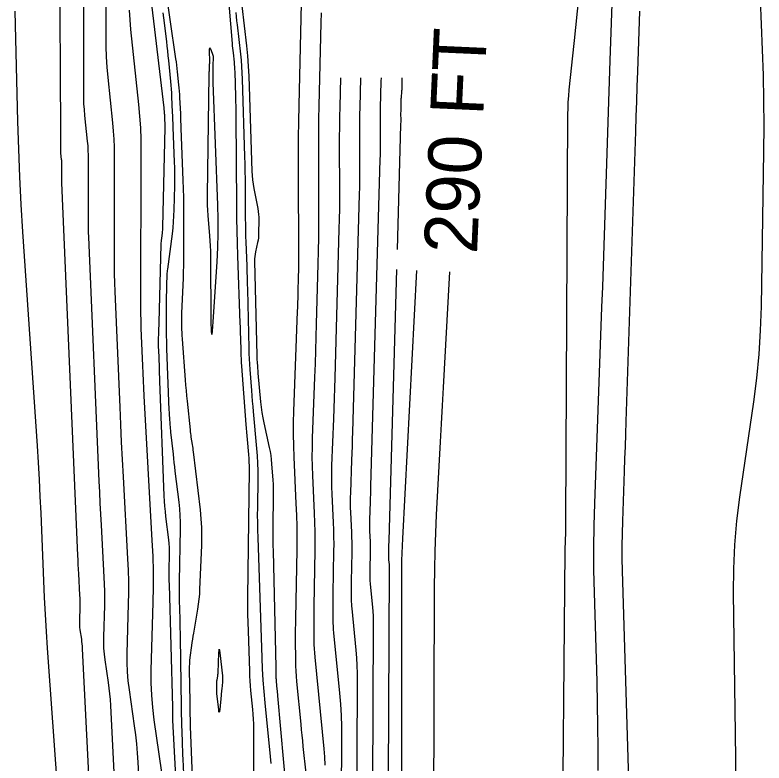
# Model space of a CAD drawing. Extents: x 1768942 to 1774819, y 723037 to 732099.
# Drawn here: x 1770850.2 to 1770934.8, y 724021.2 to 724105.6 of the extents above; entities that cross this region are included whole.
import ezdxf

# ---------------------------------------------------------------- set-up
doc = ezdxf.new("R2010")
doc.units = 0
doc.layers.add('R_Contour Annot', color=7, linetype='Continuous')
doc.layers.add('R_Contours', color=7, linetype='Continuous')

msp = doc.modelspace()

# ---------------------------------------------------------------- linework, layer by layer
at = {"layer": 'R_Contours'}
for points in [[(1770859.762, 723996.003), (1770857.868, 724034.096), (1770857.852, 724034.366), (1770857.829, 724034.635), (1770857.799, 724034.903), (1770857.763, 724035.171), (1770857.607, 724036.241), (1770857.573, 724036.509), (1770857.552, 724036.777), (1770857.542, 724037.047), (1770857.543, 724037.316), (1770857.584, 724038.787), (1770857.589, 724039.123), (1770857.588, 724039.458), (1770857.58, 724039.793), (1770857.565, 724040.128), (1770857.43, 724042.558), (1770857.402, 724043.075), (1770857.376, 724043.592), (1770857.352, 724044.109), (1770857.329, 724044.626), (1770855.534, 724086.687), (1770855.528, 724086.822), (1770855.525, 724086.957), (1770855.523, 724087.092), (1770855.523, 724087.227), (1770855.526, 724088.794), (1770855.525, 724088.919), (1770855.52, 724089.045), (1770855.512, 724089.17), (1770855.5, 724089.295), (1770855.426, 724090), (1770855.411, 724090.159), (1770855.401, 724090.319), (1770855.395, 724090.478), (1770855.394, 724090.638), (1770855.399, 724091.606), (1770855.4, 724091.821), (1770855.401, 724092.036), (1770855.4, 724092.25), (1770855.399, 724092.465), (1770855.166, 724132.363)], [(1770857.856, 724125.104), (1770857.977, 724104.494), (1770857.981, 724103.605), (1770857.982, 724102.715), (1770857.981, 724101.826), (1770857.977, 724100.936), (1770857.955, 724096.925), (1770857.961, 724096.263), (1770857.985, 724095.601), (1770858.027, 724094.94), (1770858.087, 724094.28), (1770858.396, 724091.361), (1770858.444, 724090.842), (1770858.477, 724090.323), (1770858.497, 724089.803), (1770858.503, 724089.282), (1770858.488, 724082.792), (1770858.49, 724082.231), (1770858.498, 724081.671), (1770858.513, 724081.111), (1770858.533, 724080.551), (1770859.71, 724052.988), (1770859.765, 724051.746), (1770859.824, 724050.505), (1770859.886, 724049.263), (1770859.953, 724048.022), (1770860.277, 724042.183), (1770860.314, 724041.379), (1770860.333, 724040.574), (1770860.336, 724039.77), (1770860.322, 724038.964), (1770860.225, 724035.432), (1770860.222, 724034.783), (1770860.246, 724034.137), (1770860.298, 724033.492), (1770860.378, 724032.848), (1770860.753, 724030.278), (1770860.84, 724029.635), (1770860.911, 724028.99), (1770860.966, 724028.344), (1770861.006, 724027.696), (1770862.207, 724003.529)], [(1770916.065, 724020.339), (1770916.074, 724022.853), (1770916.059, 724025.366), (1770916.02, 724027.879), (1770915.957, 724030.392), (1770915.657, 724040.443), (1770915.603, 724042.955), (1770915.591, 724045.468), (1770915.621, 724047.98), (1770915.692, 724050.492), (1770916.507, 724072.621), (1770916.592, 724074.942), (1770916.674, 724077.263), (1770916.753, 724079.584), (1770916.831, 724081.905), (1770917.136, 724091.191), (1770917.213, 724093.512), (1770917.291, 724095.833), (1770917.37, 724098.154), (1770917.45, 724100.476), (1770918.191, 724121.776)], [(1770914.509, 724113.785), (1770913.356, 724102.74), (1770913.283, 724102.045), (1770913.211, 724101.349), (1770913.139, 724100.654), (1770913.067, 724099.959), (1770912.781, 724097.177), (1770912.718, 724096.481), (1770912.672, 724095.784), (1770912.643, 724095.087), (1770912.631, 724094.388), (1770912.404, 724048.562), (1770912.401, 724048.23), (1770912.396, 724047.898), (1770912.387, 724047.566), (1770912.376, 724047.234), (1770912.304, 724045.268), (1770912.304, 724045.256), (1770912.304, 724045.243), (1770912.304, 724045.231), (1770912.304, 724045.219), (1770912.305, 724045.17), (1770912.306, 724045.158), (1770912.306, 724045.146), (1770912.306, 724045.133), (1770912.306, 724045.121), (1770911.991, 724007.151)], [(1770931.657, 724018.758), (1770931.62, 724021.635), (1770931.582, 724024.511), (1770931.374, 724040.418), (1770931.392, 724043.126), (1770931.517, 724045.827), (1770931.748, 724048.52), (1770932.085, 724051.207), (1770933.648, 724061.94), (1770933.995, 724064.627), (1770934.255, 724067.32), (1770934.428, 724070.021), (1770934.513, 724072.729), (1770934.783, 724090.222), (1770934.807, 724093.088), (1770934.793, 724095.954), (1770934.739, 724098.819), (1770934.646, 724101.684), (1770934.196, 724113.142)], [(1770864.653, 724011.056), (1770864.143, 724021.296), (1770864.08, 724022.322), (1770863.992, 724023.345), (1770863.88, 724024.367), (1770863.744, 724025.385), (1770863.149, 724029.456), (1770863.022, 724030.474), (1770862.939, 724031.496), (1770862.901, 724032.52), (1770862.907, 724033.547), (1770863.061, 724039.142), (1770863.083, 724040.416), (1770863.078, 724041.691), (1770863.047, 724042.965), (1770862.99, 724044.239), (1770862.477, 724053.485), (1770862.371, 724055.451), (1770862.271, 724057.417), (1770862.178, 724059.384), (1770862.091, 724061.35), (1770861.533, 724074.416), (1770861.497, 724075.4), (1770861.471, 724076.385), (1770861.457, 724077.371), (1770861.453, 724078.356), (1770861.48, 724089.77), (1770861.469, 724090.686), (1770861.435, 724091.601), (1770861.375, 724092.514), (1770861.291, 724093.427), (1770860.749, 724098.561), (1770860.642, 724099.721), (1770860.568, 724100.883), (1770860.526, 724102.047), (1770860.517, 724103.212), (1770860.562, 724111.374)], [(1770867.08, 724109.586), (1770868.364, 724100.671), (1770868.415, 724100.306), (1770868.463, 724099.94), (1770868.508, 724099.575), (1770868.551, 724099.209), (1770868.714, 724097.743), (1770868.752, 724097.377), (1770868.783, 724097.01), (1770868.809, 724096.642), (1770868.827, 724096.274), (1770868.903, 724094.486), (1770868.921, 724094.065), (1770868.938, 724093.645), (1770868.955, 724093.224), (1770868.971, 724092.803), (1770869.193, 724086.961), (1770869.225, 724085.997), (1770869.248, 724085.032), (1770869.261, 724084.068), (1770869.266, 724083.104), (1770869.265, 724078.724), (1770869.261, 724078.02), (1770869.25, 724077.316), (1770869.231, 724076.613), (1770869.205, 724075.909), (1770869.038, 724071.977), (1770869.033, 724071.833), (1770869.03, 724071.689), (1770869.029, 724071.545), (1770869.03, 724071.401), (1770869.037, 724070.825), (1770869.039, 724070.681), (1770869.042, 724070.537), (1770869.046, 724070.393), (1770869.051, 724070.249), (1770869.074, 724069.641), (1770869.08, 724069.491), (1770869.088, 724069.342), (1770869.097, 724069.193), (1770869.107, 724069.044), (1770869.453, 724064.438), (1770869.5, 724063.831), (1770869.552, 724063.224), (1770869.608, 724062.618), (1770869.667, 724062.012), (1770869.996, 724058.792), (1770870.019, 724058.584), (1770870.045, 724058.377), (1770870.074, 724058.17), (1770870.106, 724057.964), (1770870.24, 724057.138), (1770870.272, 724056.932), (1770870.302, 724056.725), (1770870.33, 724056.518), (1770870.356, 724056.311), (1770871.124, 724049.768), (1770871.222, 724048.762), (1770871.281, 724047.754), (1770871.3, 724046.745), (1770871.279, 724045.734), (1770871.082, 724040.808), (1770871.05, 724040.238), (1770871, 724039.669), (1770870.931, 724039.103), (1770870.843, 724038.538), (1770870.379, 724035.839), (1770870.322, 724035.497), (1770870.268, 724035.155), (1770870.218, 724034.812), (1770870.171, 724034.469), (1770869.99, 724033.095), (1770869.951, 724032.752), (1770869.924, 724032.407), (1770869.91, 724032.062), (1770869.909, 724031.716), (1770869.961, 724028.15), (1770869.973, 724027.44), (1770869.988, 724026.73), (1770870.007, 724026.021), (1770870.03, 724025.311), (1770870.226, 724019.621)], [(1770865.373, 724109.064), (1770867.028, 724095.119), (1770867.036, 724095.048), (1770867.044, 724094.976), (1770867.052, 724094.905), (1770867.059, 724094.833), (1770867.091, 724094.518), (1770867.096, 724094.461), (1770867.101, 724094.403), (1770867.105, 724094.345), (1770867.107, 724094.288), (1770867.117, 724094.057), (1770867.12, 724093.999), (1770867.122, 724093.942), (1770867.124, 724093.884), (1770867.126, 724093.826), (1770867.145, 724093.33), (1770867.148, 724093.228), (1770867.15, 724093.126), (1770867.15, 724093.024), (1770867.149, 724092.922), (1770866.901, 724081.667), (1770866.895, 724081.504), (1770866.885, 724081.341), (1770866.87, 724081.179), (1770866.851, 724081.016), (1770866.764, 724080.368), (1770866.745, 724080.206), (1770866.73, 724080.043), (1770866.719, 724079.88), (1770866.712, 724079.717), (1770866.473, 724070.91), (1770866.445, 724069.876), (1770866.416, 724068.843), (1770866.411, 724068.585), (1770866.411, 724068.327), (1770866.414, 724068.069), (1770866.422, 724067.81), (1770866.495, 724065.905), (1770866.51, 724065.501), (1770866.525, 724065.097), (1770866.541, 724064.694), (1770866.556, 724064.29), (1770867.057, 724051.336), (1770867.086, 724050.754), (1770867.126, 724050.172), (1770867.179, 724049.591), (1770867.244, 724049.011), (1770867.567, 724046.365), (1770867.61, 724045.949), (1770867.639, 724045.533), (1770867.653, 724045.115), (1770867.652, 724044.697), (1770867.619, 724043.024), (1770867.614, 724042.605), (1770867.613, 724042.187), (1770867.617, 724041.768), (1770867.626, 724041.35), (1770868.003, 724027.481), (1770868.006, 724027.378), (1770868.008, 724027.276), (1770868.01, 724027.174), (1770868.012, 724027.072), (1770868.019, 724026.541), (1770868.02, 724026.5), (1770868.021, 724026.458), (1770868.022, 724026.417), (1770868.023, 724026.375), (1770868.029, 724026.209), (1770868.03, 724026.168), (1770868.032, 724026.127), (1770868.034, 724026.085), (1770868.036, 724026.044), (1770868.457, 724017.573)], [(1770877.215, 724014.005), (1770877.205, 724025.07), (1770877.197, 724025.611), (1770877.177, 724026.151), (1770877.143, 724026.691), (1770877.095, 724027.23), (1770876.879, 724029.384), (1770876.829, 724029.923), (1770876.789, 724030.463), (1770876.757, 724031.003), (1770876.735, 724031.543), (1770876.582, 724036.106), (1770876.556, 724037.047), (1770876.541, 724037.988), (1770876.535, 724038.929), (1770876.541, 724039.871), (1770876.703, 724054.289), (1770876.703, 724054.717), (1770876.692, 724055.143), (1770876.669, 724055.569), (1770876.637, 724055.995), (1770876.483, 724057.697), (1770876.446, 724058.123), (1770876.41, 724058.549), (1770876.375, 724058.975), (1770876.342, 724059.401), (1770875.842, 724065.98), (1770875.814, 724066.384), (1770875.791, 724066.788), (1770875.774, 724067.192), (1770875.762, 724067.597), (1770875.723, 724069.216), (1770875.713, 724069.62), (1770875.701, 724070.025), (1770875.688, 724070.429), (1770875.673, 724070.834), (1770875.387, 724078.448), (1770875.34, 724079.852), (1770875.304, 724081.256), (1770875.28, 724082.66), (1770875.266, 724084.065), (1770875.21, 724094.193), (1770875.205, 724094.748), (1770875.197, 724095.303), (1770875.185, 724095.858), (1770875.17, 724096.414), (1770875.084, 724099.212), (1770875.074, 724099.478), (1770875.057, 724099.743), (1770875.036, 724100.008), (1770875.008, 724100.273), (1770874.889, 724101.331), (1770874.86, 724101.595), (1770874.833, 724101.86), (1770874.809, 724102.125), (1770874.786, 724102.39), (1770874.283, 724108.645)], [(1770875.594, 724108.942), (1770876.364, 724102.132), (1770876.481, 724100.987), (1770876.575, 724099.84), (1770876.646, 724098.691), (1770876.693, 724097.541), (1770876.985, 724087.971), (1770877.01, 724087.479), (1770877.055, 724086.99), (1770877.121, 724086.502), (1770877.206, 724086.017), (1770877.652, 724083.762), (1770877.708, 724083.436), (1770877.746, 724083.109), (1770877.767, 724082.781), (1770877.77, 724082.451), (1770877.747, 724081.002), (1770877.736, 724080.735), (1770877.711, 724080.469), (1770877.673, 724080.205), (1770877.621, 724079.942), (1770877.386, 724078.895), (1770877.335, 724078.632), (1770877.301, 724078.368), (1770877.283, 724078.102), (1770877.281, 724077.835), (1770877.534, 724067.165), (1770877.539, 724067.002), (1770877.546, 724066.838), (1770877.556, 724066.675), (1770877.567, 724066.511), (1770877.617, 724065.858), (1770877.629, 724065.695), (1770877.642, 724065.531), (1770877.656, 724065.368), (1770877.671, 724065.205), (1770877.964, 724061.945), (1770878.027, 724061.349), (1770878.11, 724060.755), (1770878.21, 724060.165), (1770878.33, 724059.577), (1770878.942, 724056.802), (1770879.034, 724056.346), (1770879.109, 724055.889), (1770879.168, 724055.428), (1770879.21, 724054.966), (1770879.346, 724053.11), (1770879.375, 724052.646), (1770879.394, 724052.182), (1770879.403, 724051.718), (1770879.402, 724051.253), (1770879.36, 724047.925), (1770879.354, 724047.215), (1770879.355, 724046.506), (1770879.362, 724045.796), (1770879.376, 724045.086), (1770879.694, 724032.001), (1770879.697, 724031.866), (1770879.699, 724031.73), (1770879.7, 724031.595), (1770879.7, 724031.459), (1770879.699, 724030.917), (1770879.701, 724030.782), (1770879.706, 724030.647), (1770879.715, 724030.511), (1770879.726, 724030.377), (1770879.812, 724029.525), (1770879.831, 724029.338), (1770879.849, 724029.151), (1770879.867, 724028.964), (1770879.884, 724028.777), (1770880.898, 724017.509)], [(1770882.552, 724106.919), (1770882.276, 724095.421), (1770882.238, 724093.601), (1770882.214, 724091.781), (1770882.203, 724089.961), (1770882.205, 724088.14), (1770882.25, 724078.232), (1770882.25, 724077.725), (1770882.246, 724077.217), (1770882.238, 724076.71), (1770882.226, 724076.203), (1770882.168, 724074.176), (1770882.153, 724073.669), (1770882.137, 724073.162), (1770882.119, 724072.655), (1770882.101, 724072.148), (1770881.684, 724060.916), (1770881.649, 724059.611), (1770881.642, 724058.307), (1770881.663, 724057.003), (1770881.711, 724055.699), (1770881.961, 724050.484), (1770882.012, 724049.18), (1770882.042, 724047.875), (1770882.051, 724046.571), (1770882.039, 724045.266), (1770881.9, 724037.503), (1770881.892, 724036.91), (1770881.886, 724036.317), (1770881.885, 724035.724), (1770881.887, 724035.131), (1770881.903, 724032.759), (1770881.914, 724032.167), (1770881.938, 724031.575), (1770881.976, 724030.984), (1770882.027, 724030.393), (1770882.502, 724025.581), (1770882.564, 724024.953), (1770882.626, 724024.324), (1770882.689, 724023.696), (1770882.753, 724023.068), (1770883.057, 724020.056)], [(1770850.233, 724106.044), (1770850.53, 724093.578), (1770850.621, 724090.463), (1770850.746, 724087.348), (1770850.905, 724084.236), (1770851.097, 724081.124), (1770852.72, 724056.999), (1770852.842, 724055.096), (1770852.951, 724053.192), (1770853.048, 724051.287), (1770853.133, 724049.382), (1770853.447, 724041.76), (1770853.533, 724039.855), (1770853.634, 724037.951), (1770853.749, 724036.047), (1770853.879, 724034.145), (1770856.967, 723991.357)], [(1770863.121, 724106.164), (1770863.191, 724105.065), (1770863.291, 724103.967), (1770864.187, 724095.492), (1770864.307, 724094.186), (1770864.392, 724092.879), (1770864.442, 724091.569), (1770864.456, 724090.258), (1770864.416, 724072.793), (1770864.419, 724071.946), (1770864.431, 724071.1), (1770864.453, 724070.253), (1770864.485, 724069.407), (1770864.629, 724066.022), (1770864.667, 724065.175), (1770864.707, 724064.329), (1770864.75, 724063.483), (1770864.795, 724062.638), (1770865.702, 724046.295), (1770865.781, 724044.552), (1770865.823, 724042.808), (1770865.829, 724041.063), (1770865.8, 724039.319), (1770865.589, 724031.662), (1770865.581, 724030.257), (1770865.633, 724028.855), (1770865.746, 724027.457), (1770865.919, 724026.063), (1770867.052, 724018.318)], [(1770875.172, 724105.901), (1770875.216, 724105.43), (1770875.263, 724104.959), (1770875.315, 724104.489), (1770875.686, 724101.203), (1770875.758, 724100.498), (1770875.816, 724099.792), (1770875.86, 724099.085), (1770875.889, 724098.377), (1770876.156, 724089.63), (1770876.179, 724088.797), (1770876.196, 724087.964), (1770876.209, 724087.131), (1770876.216, 724086.297), (1770876.236, 724082.631), (1770876.243, 724081.965), (1770876.254, 724081.298), (1770876.271, 724080.632), (1770876.294, 724079.966), (1770876.394, 724077.301), (1770876.418, 724076.635), (1770876.439, 724075.969), (1770876.459, 724075.302), (1770876.476, 724074.636), (1770876.633, 724068.009), (1770876.651, 724067.411), (1770876.677, 724066.813), (1770876.711, 724066.216), (1770876.752, 724065.619), (1770876.933, 724063.233), (1770876.98, 724062.637), (1770877.028, 724062.04), (1770877.079, 724061.444), (1770877.131, 724060.848), (1770877.506, 724056.69), (1770877.57, 724055.855), (1770877.614, 724055.02), (1770877.636, 724054.183), (1770877.637, 724053.346), (1770877.599, 724049.995), (1770877.594, 724049.158), (1770877.599, 724048.32), (1770877.613, 724047.483), (1770877.636, 724046.645), (1770878.089, 724033.083), (1770878.142, 724031.805), (1770878.217, 724030.528), (1770878.313, 724029.252), (1770878.43, 724027.978), (1770879.037, 724021.935), (1770879.107, 724021.136)], [(1770920.759, 724106.037), (1770920.523, 724099.249), (1770920.464, 724097.552), (1770920.406, 724095.855), (1770920.349, 724094.158), (1770920.293, 724092.461), (1770919.217, 724059.726), (1770919.17, 724058.322), (1770919.122, 724056.919), (1770919.072, 724055.516), (1770919.021, 724054.112), (1770918.815, 724048.499), (1770918.775, 724047.096), (1770918.758, 724045.692), (1770918.765, 724044.289), (1770918.795, 724042.885), (1770919.832, 724008.14)], [(1770866.934, 724105.836), (1770867.006, 724105.301), (1770867.324, 724102.618), (1770867.387, 724102.082), (1770867.447, 724101.546), (1770867.504, 724101.009), (1770867.559, 724100.473), (1770867.797, 724098.113), (1770867.837, 724097.683), (1770867.871, 724097.251), (1770867.899, 724096.82), (1770867.92, 724096.387), (1770867.994, 724094.658), (1770868.012, 724094.225), (1770868.03, 724093.793), (1770868.047, 724093.361), (1770868.064, 724092.928), (1770868.211, 724089.037), (1770868.232, 724088.36), (1770868.242, 724087.682), (1770868.243, 724087.005), (1770868.233, 724086.327), (1770868.173, 724083.616), (1770868.149, 724082.939), (1770868.106, 724082.263), (1770868.045, 724081.589), (1770867.965, 724080.917), (1770867.435, 724076.942), (1770867.417, 724076.789), (1770867.402, 724076.635), (1770867.392, 724076.481), (1770867.386, 724076.326), (1770867.352, 724075.089), (1770867.302, 724073.23), (1770867.294, 724072.868), (1770867.289, 724072.507), (1770867.288, 724072.145), (1770867.291, 724071.784), (1770867.315, 724069.795), (1770867.321, 724069.343), (1770867.331, 724068.891), (1770867.344, 724068.439), (1770867.359, 724067.988), (1770867.622, 724060.996), (1770867.63, 724060.789), (1770867.641, 724060.582), (1770867.654, 724060.375), (1770867.668, 724060.169), (1770867.73, 724059.342), (1770867.747, 724059.136), (1770867.765, 724058.929), (1770867.785, 724058.723), (1770867.806, 724058.517), (1770868.076, 724056.052), (1770868.129, 724055.573), (1770868.183, 724055.094), (1770868.24, 724054.615), (1770868.297, 724054.136), (1770868.727, 724050.615), (1770868.805, 724049.868), (1770868.857, 724049.119), (1770868.882, 724048.37), (1770868.88, 724047.619), (1770868.765, 724041.69), (1770868.758, 724041.161), (1770868.757, 724040.632), (1770868.762, 724040.103), (1770868.773, 724039.575), (1770868.831, 724037.46), (1770868.844, 724036.931), (1770868.856, 724036.402), (1770868.866, 724035.874), (1770868.875, 724035.345), (1770868.986, 724027.588), (1770868.995, 724027.091), (1770869.006, 724026.594), (1770869.019, 724026.097), (1770869.035, 724025.6), (1770869.103, 724023.613), (1770869.121, 724023.117), (1770869.141, 724022.62), (1770869.163, 724022.123), (1770869.187, 724021.627), (1770869.351, 724018.332)], [(1770885.269, 724020.94), (1770885.213, 724021.877), (1770885.133, 724022.812), (1770884.114, 724033.141), (1770884.073, 724033.619), (1770884.042, 724034.097), (1770884.022, 724034.576), (1770884.014, 724035.056), (1770884.001, 724036.976), (1770883.999, 724037.456), (1770884, 724037.936), (1770884.004, 724038.416), (1770884.011, 724038.896), (1770884.123, 724045.178), (1770884.134, 724046.234), (1770884.126, 724047.29), (1770884.102, 724048.346), (1770884.06, 724049.401), (1770883.859, 724053.623), (1770883.819, 724054.678), (1770883.803, 724055.733), (1770883.808, 724056.789), (1770883.836, 724057.845), (1770884.093, 724064.75), (1770884.147, 724066.253), (1770884.198, 724067.756), (1770884.246, 724069.26), (1770884.29, 724070.763), (1770884.483, 724077.506), (1770884.52, 724078.992), (1770884.544, 724080.478), (1770884.555, 724081.964), (1770884.555, 724083.451), (1770884.528, 724089.396), (1770884.526, 724090.883), (1770884.535, 724092.369), (1770884.555, 724093.855), (1770884.585, 724095.341), (1770884.811, 724104.729), (1770884.847, 724105.845)], [(1770886.974, 724098.536), (1770886.895, 724095.261), (1770886.871, 724094.109), (1770886.856, 724092.957), (1770886.849, 724091.805), (1770886.85, 724090.652), (1770886.871, 724086.043), (1770886.872, 724084.89), (1770886.863, 724083.738), (1770886.844, 724082.586), (1770886.816, 724081.434), (1770886.336, 724064.649), (1770886.302, 724063.5), (1770886.265, 724062.351), (1770886.226, 724061.202), (1770886.185, 724060.053), (1770885.989, 724054.774), (1770885.967, 724053.967), (1770885.963, 724053.16), (1770885.976, 724052.353), (1770886.006, 724051.546), (1770886.16, 724048.319), (1770886.192, 724047.512), (1770886.21, 724046.705), (1770886.216, 724045.898), (1770886.208, 724045.091), (1770886.123, 724040.288), (1770886.117, 724039.921), (1770886.114, 724039.554), (1770886.113, 724039.187), (1770886.114, 724038.82), (1770886.124, 724037.353), (1770886.131, 724036.986), (1770886.146, 724036.62), (1770886.169, 724036.254), (1770886.201, 724035.888), (1770886.873, 724029.077), (1770886.98, 724027.819), (1770887.056, 724026.56), (1770887.098, 724025.299), (1770887.108, 724024.037), (1770887.042, 724010.528)], [(1770888.793, 724005.544), (1770888.916, 724030.436), (1770888.909, 724031.31), (1770888.879, 724032.182), (1770888.827, 724033.053), (1770888.753, 724033.923), (1770888.288, 724038.636), (1770888.266, 724038.889), (1770888.25, 724039.142), (1770888.239, 724039.395), (1770888.235, 724039.649), (1770888.228, 724040.665), (1770888.227, 724040.919), (1770888.228, 724041.172), (1770888.23, 724041.426), (1770888.234, 724041.68), (1770888.293, 724045.003), (1770888.298, 724045.562), (1770888.294, 724046.12), (1770888.282, 724046.679), (1770888.259, 724047.237), (1770888.153, 724049.47), (1770888.132, 724050.028), (1770888.123, 724050.586), (1770888.126, 724051.144), (1770888.141, 724051.703), (1770888.277, 724055.356), (1770888.305, 724056.15), (1770888.332, 724056.945), (1770888.358, 724057.741), (1770888.381, 724058.536), (1770889.149, 724085.362), (1770889.169, 724086.18), (1770889.182, 724086.998), (1770889.188, 724087.817), (1770889.188, 724088.635), (1770889.173, 724091.908), (1770889.172, 724092.727), (1770889.177, 724093.545), (1770889.188, 724094.363), (1770889.205, 724095.181), (1770889.285, 724098.525)], [(1770890.544, 724000.561), (1770890.723, 724036.835), (1770890.719, 724037.32), (1770890.703, 724037.804), (1770890.674, 724038.287), (1770890.633, 724038.77), (1770890.375, 724041.384), (1770890.363, 724041.524), (1770890.354, 724041.665), (1770890.348, 724041.805), (1770890.345, 724041.946), (1770890.342, 724042.509), (1770890.341, 724042.65), (1770890.341, 724042.791), (1770890.343, 724042.932), (1770890.345, 724043.072), (1770890.378, 724044.916), (1770890.381, 724045.226), (1770890.379, 724045.535), (1770890.371, 724045.845), (1770890.359, 724046.155), (1770890.3, 724047.393), (1770890.288, 724047.703), (1770890.283, 724048.012), (1770890.285, 724048.322), (1770890.293, 724048.632), (1770890.369, 724050.658), (1770890.385, 724051.099), (1770890.4, 724051.54), (1770890.414, 724051.981), (1770890.427, 724052.422), (1770891.481, 724089.29), (1770891.493, 724089.775), (1770891.501, 724090.259), (1770891.505, 724090.743), (1770891.504, 724091.227), (1770891.496, 724093.165), (1770891.495, 724093.649), (1770891.498, 724094.133), (1770891.504, 724094.617), (1770891.514, 724095.102), (1770891.588, 724098.16), (1770891.599, 724098.514)], [(1770893.411, 724079.141), (1770893.814, 724093.219), (1770893.817, 724093.369), (1770893.82, 724093.519), (1770893.821, 724093.669), (1770893.821, 724093.82), (1770893.818, 724094.421), (1770893.818, 724094.571), (1770893.819, 724094.721), (1770893.821, 724094.871), (1770893.824, 724095.022), (1770893.847, 724095.971), (1770893.851, 724096.083), (1770893.856, 724096.196), (1770893.864, 724096.309), (1770893.873, 724096.421), (1770893.915, 724096.871), (1770893.925, 724096.983), (1770893.931, 724097.096), (1770893.935, 724097.208), (1770893.936, 724097.321), (1770893.932, 724098.503)], [(1770892.295, 723995.577), (1770892.53, 724043.235), (1770892.53, 724043.33), (1770892.527, 724043.426), (1770892.521, 724043.521), (1770892.513, 724043.616), (1770892.462, 724044.132), (1770892.459, 724044.159), (1770892.458, 724044.187), (1770892.457, 724044.215), (1770892.456, 724044.242), (1770892.455, 724044.354), (1770892.455, 724044.381), (1770892.455, 724044.409), (1770892.455, 724044.437), (1770892.456, 724044.465), (1770892.462, 724044.828), (1770892.463, 724044.889), (1770892.463, 724044.95), (1770892.461, 724045.011), (1770892.459, 724045.072), (1770892.447, 724045.317), (1770892.445, 724045.378), (1770892.444, 724045.439), (1770892.444, 724045.5), (1770892.446, 724045.561), (1770892.461, 724045.961), (1770892.464, 724046.047), (1770892.467, 724046.134), (1770892.469, 724046.221), (1770892.472, 724046.308), (1770893.346, 724076.88)], [(1770895.563, 724076.78), (1770893.971, 724046.535), (1770893.932, 724045.701), (1770893.904, 724044.867), (1770893.886, 724044.033), (1770893.878, 724043.198), (1770893.869, 724039.859), (1770893.867, 724039.024), (1770893.865, 724038.189), (1770893.864, 724037.354), (1770893.863, 724036.52), (1770893.839, 723997)], [(1770899.303, 724076.612), (1770898.68, 724065.631), (1770898.565, 724063.579), (1770898.451, 724061.528), (1770898.34, 724059.477), (1770898.231, 724057.425), (1770897.799, 724049.219), (1770897.704, 724047.167), (1770897.634, 724045.115), (1770897.59, 724043.061), (1770897.571, 724041.007), (1770897.497, 724015.33)]]:
    msp.add_lwpolyline(points, dxfattribs=at)
for points in [[(1770872.33, 724078.964), (1770872.31, 724079.54), (1770872.278, 724080.116), (1770872.235, 724080.691), (1770872.043, 724082.99), (1770872.002, 724083.565), (1770871.975, 724084.14), (1770871.962, 724084.716), (1770871.964, 724085.292), (1770872.167, 724098.856), (1770872.169, 724098.964), (1770872.172, 724099.072), (1770872.176, 724099.181), (1770872.181, 724099.289), (1770872.204, 724099.723), (1770872.209, 724099.831), (1770872.212, 724099.939), (1770872.214, 724100.048), (1770872.215, 724100.156), (1770872.214, 724101.758), (1770872.22, 724101.853), (1770872.238, 724101.888), (1770872.269, 724101.863), (1770872.312, 724101.778), (1770872.509, 724101.316), (1770872.551, 724101.199), (1770872.58, 724101.08), (1770872.597, 724100.958), (1770872.6, 724100.834), (1770872.574, 724099.88), (1770872.57, 724099.723), (1770872.567, 724099.567), (1770872.565, 724099.411), (1770872.564, 724099.254), (1770872.562, 724098.628), (1770872.562, 724098.472), (1770872.564, 724098.316), (1770872.567, 724098.159), (1770872.573, 724098.003), (1770873.104, 724084.159), (1770873.145, 724082.557), (1770873.145, 724080.954), (1770873.104, 724079.353), (1770873.022, 724077.752), (1770872.59, 724070.989), (1770872.509, 724069.924), (1770872.449, 724069.569), (1770872.409, 724069.926), (1770872.389, 724070.995), (1770872.339, 724078.388)], [(1770873.017, 724030.272), (1770873.023, 724030.374), (1770873.035, 724030.475), (1770873.05, 724030.576), (1770873.119, 724030.98), (1770873.135, 724031.081), (1770873.147, 724031.183), (1770873.156, 724031.284), (1770873.162, 724031.386), (1770873.252, 724033.629), (1770873.271, 724033.935), (1770873.298, 724034.038), (1770873.331, 724033.937), (1770873.37, 724033.633), (1770873.646, 724031.037), (1770873.66, 724030.854), (1770873.665, 724030.672), (1770873.661, 724030.489), (1770873.647, 724030.306), (1770873.573, 724029.575), (1770873.555, 724029.393), (1770873.537, 724029.21), (1770873.52, 724029.027), (1770873.504, 724028.844), (1770873.362, 724027.242), (1770873.332, 724026.996), (1770873.3, 724026.913), (1770873.267, 724026.995), (1770873.232, 724027.24), (1770873.039, 724028.995), (1770873.026, 724029.133), (1770873.017, 724029.27), (1770873.012, 724029.408), (1770873.01, 724029.546), (1770873.014, 724030.17)]]:
    msp.add_lwpolyline(points, close=True, dxfattribs=at)

# ---------------------------------------------------------------- texts
at = {"layer": 'R_Contour Annot'}
msp.add_text('290 FT', height=6, rotation=87.42714, dxfattribs=at).set_placement((1770902.395, 724078.578))

doc.saveas('drawing.dxf')
